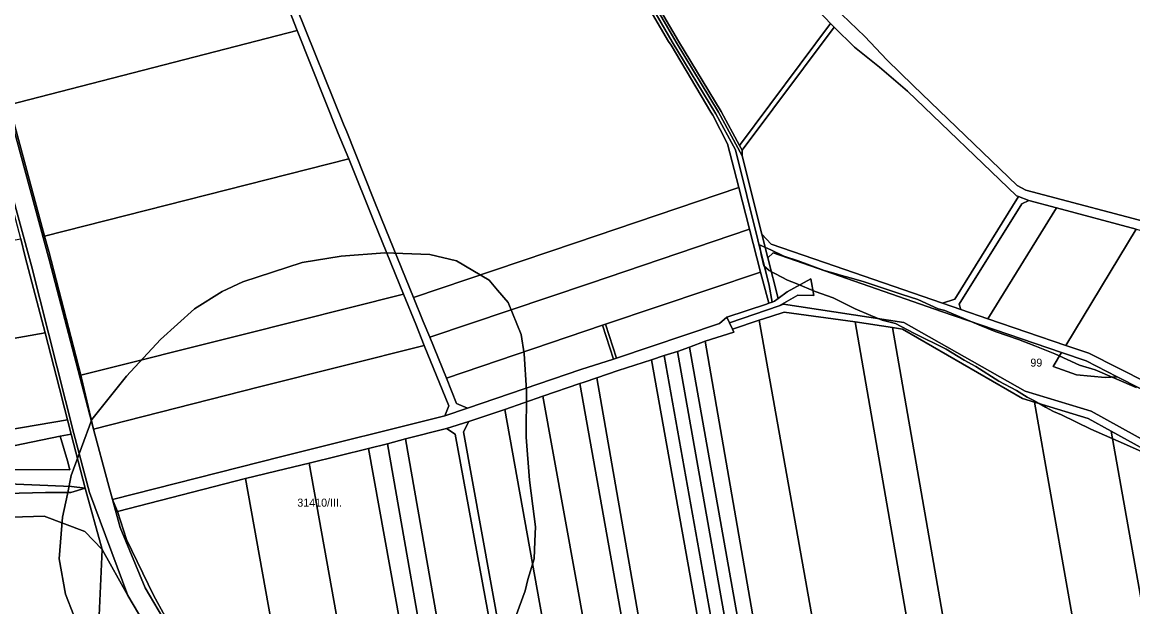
# Model space of a CAD drawing. Extents: x -541351 to -537540, y -1162694 to -1159725.
# Drawn here: x -539563 to -538870, y -1161193 to -1160828 of the extents above; entities that cross this region are included whole.
import ezdxf

# ---------------------------------------------------------------- set-up
doc = ezdxf.new("R2010")
doc.units = 0
for name, color, linetype in [('95560013', 7, 'Continuous'), ('95590013', 7, 'Continuous'), ('95600013', 7, 'Continuous'), ('95610013', 7, 'Continuous'), ('95620013', 7, 'Continuous'), ('95630013', 7, 'Continuous'), ('95640013', 7, 'Continuous'), ('95660013', 7, 'Continuous')]:
    doc.layers.add(name, color=color, linetype=linetype)

msp = doc.modelspace()

# ---------------------------------------------------------------- linework, layer by layer
at = {"layer": '95560013'}
for points in [[(-538936.41, -1160932.83), (-538941.86, -1160929.93), (-539006.76, -1160867.53), (-539023.31, -1160851.37), (-539036.93, -1160836.79), (-539051.37, -1160823.12), (-539062.82, -1160809.24), (-539062.72, -1160804.09), (-539047.66, -1160784.3), (-538944.37, -1160644.78), (-538780.28, -1160688.55), (-538705.74, -1160708.79), (-538703.32, -1160712.7), (-538773.26, -1160973.06), (-538776.17, -1160975.29), (-538851.4, -1160955.36)], [(-539571.49, -1160879.49), (-539576.96, -1160860.94), (-539589.32, -1160816.2), (-539599.23, -1160779.87), (-539429.99, -1160738.47), (-539398.34, -1160816), (-539391.52, -1160833.04)], [(-539319, -1160999.73), (-539338.81, -1160950.75), (-539344.03, -1160937.82), (-539360.64, -1160896.43), (-539362.62, -1160891.49), (-539391.92, -1160818.73), (-539393.55, -1160815.07), (-539200.33, -1160766.57), (-539198.59, -1160770.28), (-539195.58, -1160776.25), (-539186.06, -1160794.51), (-539159.57, -1160840.01), (-539158.05, -1160842.31), (-539133.25, -1160884.16), (-539132.01, -1160885.98), (-539122.7, -1160903.87), (-539115.7, -1160931.14), (-539217.82, -1160965.59)], [(-539056.08, -1160831.08), (-539113.65, -1160907.77), (-539115.26, -1160904.98), (-539058.38, -1160828.79)], [(-539549.36, -1160961.61), (-539571.49, -1160879.49), (-539391.52, -1160833.04), (-539365.89, -1160897.32), (-539359.32, -1160913.21)], [(-538940.95, -1160936.8), (-538980.86, -1161000.78), (-538988.49, -1161003.42), (-539062.15, -1160978.04), (-539095.57, -1160966.53), (-539101.33, -1160960.2), (-539113.58, -1160911.28), (-539113.65, -1160907.77), (-539056.08, -1160831.08), (-539043.56, -1160843.53), (-539027.86, -1160856), (-539010.44, -1160871.03), (-538942.34, -1160936.25)], [(-539359.32, -1160913.21), (-539343.7, -1160952.09), (-539325.13, -1160997.71), (-539426.06, -1161023.06), (-539526.79, -1161048.34), (-539546.7, -1160971.15), (-539549.36, -1160961.61)], [(-539308.65, -1161024.67), (-539312.86, -1161014.72), (-539319, -1160999.73), (-539217.82, -1160965.59), (-539115.7, -1160931.14), (-539109.11, -1160957.17), (-539208.98, -1160991.01)], [(-538977.08, -1161007.35), (-538988.49, -1161003.42), (-538980.86, -1161000.78), (-538940.95, -1160936.8), (-538934.54, -1160939.32), (-538938.99, -1160941.25), (-538978.06, -1161004.06)], [(-538960.29, -1161013.08), (-538977.08, -1161007.35), (-538978.06, -1161004.06), (-538938.99, -1160941.25), (-538934.54, -1160939.32), (-538917.2, -1160943.93)], [(-539200.9, -1161017.09), (-539298.21, -1161050.27), (-539308.65, -1161024.67), (-539208.98, -1160991.01), (-539109.11, -1160957.17), (-539102.14, -1160984.03), (-539199, -1161016.45)], [(-538693.8, -1161093.06), (-538731.97, -1161099.47), (-538764.06, -1161100.05), (-538769.83, -1161098.84), (-538897.07, -1161034.68), (-538911.55, -1161029.73), (-538867.63, -1160957.22), (-538852.58, -1160961.1), (-538705.49, -1161000.19), (-538660, -1161012.28), (-538629.09, -1161020.49), (-538626.83, -1161024.07), (-538630.91, -1161069.95), (-538631.75, -1161079.36), (-538634.66, -1161082.91)], [(-539740.05, -1161033.33), (-539738.55, -1161002.02), (-539745.1, -1160994.72), (-539564.23, -1160963.09), (-539561.45, -1160974.35), (-539548.91, -1161021.98), (-539735.79, -1161055.02)], [(-539127.84, -1161016.1), (-539192.09, -1161037.76), (-539199, -1161016.45), (-539102.14, -1160984.03), (-539097.08, -1161003.42), (-539098.52, -1161003.9), (-539123.2, -1161012.21)], [(-539526.79, -1161048.34), (-539426.06, -1161023.06), (-539325.13, -1160997.71), (-539317.56, -1161016.54), (-539312.2, -1161029.72), (-539415.08, -1161055.7), (-539518.85, -1161082.11), (-539526.32, -1161050.29)], [(-538994.31, -1161295.03), (-539045.37, -1161294.34), (-539053.1, -1161294.23), (-539103, -1161013.98), (-539095.66, -1161011.59), (-539087.45, -1161008.9), (-539043.01, -1161015.07)], [(-539292.12, -1161065.98), (-539298.21, -1161050.27), (-539200.9, -1161017.09), (-539194.02, -1161038.27), (-539214.32, -1161044.82), (-539285.11, -1161068.9)], [(-539200.9, -1161017.09), (-539199, -1161016.45), (-539192.09, -1161037.76), (-539194.02, -1161038.27)], [(-539118.78, -1161021.38), (-539119.66, -1161019.55), (-539103, -1161013.98), (-539053.1, -1161294.23), (-539084.18, -1161293.8), (-539090.47, -1161293.43), (-539136.75, -1161027.11)], [(-538972.25, -1161295.43), (-538994.31, -1161295.03), (-539043.01, -1161015.07), (-539019.68, -1161018.63), (-538971.53, -1161295.41)], [(-539648.73, -1161061.97), (-539660.98, -1161063.8), (-539674.91, -1161065.89), (-539700.61, -1161069.8), (-539704.64, -1161070.36), (-539731.15, -1161074.48), (-539735.79, -1161055.02), (-539548.91, -1161021.98), (-539539.99, -1161056.65), (-539536.99, -1161068.99), (-539534.97, -1161076.16), (-539620.86, -1161090.73), (-539621.9, -1161085.23), (-539626.91, -1161058.7)], [(-539509.83, -1161115.28), (-539518.85, -1161082.11), (-539415.08, -1161055.7), (-539312.2, -1161029.72), (-539296.85, -1161067.44), (-539299.45, -1161073.62), (-539401.26, -1161099.09), (-539506.91, -1161125.99)], [(-539154.11, -1161033.45), (-539146.43, -1161030.83), (-539099.9, -1161293.1), (-539108, -1161292.84)], [(-539090.47, -1161293.43), (-539099.9, -1161293.1), (-539146.43, -1161030.83), (-539136.75, -1161027.11)], [(-539116.49, -1161292.48), (-539124.88, -1161292.22), (-539170.2, -1161038.79), (-539162.3, -1161036.06)], [(-539108, -1161292.84), (-539116.49, -1161292.48), (-539162.3, -1161036.06), (-539154.11, -1161033.45)], [(-539146.97, -1161291.52), (-539161.16, -1161290.98), (-539162.36, -1161290.96), (-539204.4, -1161050.02), (-539191.17, -1161045.44), (-539170.2, -1161038.79), (-539124.88, -1161292.22)], [(-539212.36, -1161052.68), (-539204.4, -1161050.02), (-539162.36, -1161290.96), (-539173.01, -1161288.87), (-539215.11, -1161053.62)], [(-539238.1, -1161061.49), (-539215.11, -1161053.62), (-539173.01, -1161288.87), (-539193.16, -1161285.12), (-539197.72, -1161284.19)], [(-538844.86, -1161298.63), (-538877.93, -1161297.24), (-538890.19, -1161296.72), (-538931.09, -1161065.09), (-538897.58, -1161075.44), (-538883.22, -1161083.36)], [(-539261.83, -1161069.68), (-539224.32, -1161278.28), (-539240.79, -1161274.83), (-539253.51, -1161272.15), (-539287.68, -1161083.7), (-539284.33, -1161077.27)], [(-539586.15, -1161096.06), (-539583.98, -1161107.12), (-539583.51, -1161109.53), (-539583.24, -1161110.91), (-539582.3, -1161115.66), (-539614.61, -1161116.17), (-539620.86, -1161090.73), (-539534.97, -1161076.16), (-539532.67, -1161085.08), (-539539.6, -1161086.5)], [(-539292.9, -1161085.27), (-539298.4, -1161081.63), (-539284.33, -1161077.27), (-539287.68, -1161083.7), (-539253.51, -1161272.15), (-539258.85, -1161270.91)], [(-539298.4, -1161081.63), (-539292.9, -1161085.27), (-539258.85, -1161270.91), (-539293.08, -1161263.8), (-539323.99, -1161088.08)], [(-538805.75, -1161126.05), (-538769.12, -1161120.18), (-538766.35, -1161119.74), (-538734.05, -1161301.26), (-538762.23, -1161300.41), (-538824.88, -1161299.47), (-538844.86, -1161298.63), (-538883.22, -1161083.36)], [(-539305.49, -1161261.12), (-539308.15, -1161260.59), (-539317.28, -1161258.8), (-539346.97, -1161094.08), (-539335.13, -1161091.14)], [(-539293.08, -1161263.8), (-539305.49, -1161261.12), (-539335.13, -1161091.14), (-539323.99, -1161088.08)], [(-539384.02, -1161103.38), (-539346.97, -1161094.08), (-539317.28, -1161258.8), (-539357.66, -1161250.4)], [(-539398.81, -1161106.88), (-539384.02, -1161103.38), (-539357.66, -1161250.4), (-539360.48, -1161249.96), (-539400.77, -1161241.37), (-539423.77, -1161112.8)], [(-539414.3, -1161238.64), (-539438.49, -1161233.39), (-539443.01, -1161208.8), (-539466.8, -1161212.37), (-539481.41, -1161185.77), (-539498.11, -1161150.86), (-539503.79, -1161133.46), (-539423.77, -1161112.8), (-539400.77, -1161241.37)], [(-539516.59, -1161225.93), (-539513.32, -1161157.12), (-539497.36, -1161186), (-539472.01, -1161228.75)]]:
    msp.add_lwpolyline(points, close=True, dxfattribs=at)
msp.add_lwpolyline([(-539391.92, -1160818.73), (-539362.62, -1160891.49), (-539360.64, -1160896.43), (-539344.03, -1160937.82), (-539338.81, -1160950.75), (-539319, -1160999.73), (-539312.86, -1161014.72), (-539308.65, -1161024.67), (-539298.21, -1161050.27), (-539292.12, -1161065.98), (-539285.11, -1161068.9), (-539299.45, -1161073.62), (-539296.85, -1161067.44), (-539312.2, -1161029.72), (-539317.56, -1161016.54), (-539325.13, -1160997.71), (-539343.7, -1160952.09), (-539359.32, -1160913.21), (-539365.89, -1160897.32), (-539391.52, -1160833.04), (-539398.34, -1160816)], dxfattribs=at)
at = {"layer": '95590013'}
msp.add_lwpolyline([(-539513.32, -1161157.12), (-539516.59, -1161225.93), (-539557.69, -1161223.11), (-539601.36, -1161219.9), (-539597.06, -1161137.85), (-539549.61, -1161136.48), (-539524.21, -1161145.9)], close=True, dxfattribs=at)
at = {"layer": '95600013'}
msp.add_lwpolyline([(-538917.2, -1160943.93), (-538867.63, -1160957.22), (-538911.55, -1161029.73), (-538960.29, -1161013.08)], close=True, dxfattribs=at)
at = {"layer": '95610013'}
for points in [[(-539083, -1160802.43), (-539058.38, -1160828.79), (-539115.26, -1160904.98), (-539126.83, -1160883.61), (-539153.38, -1160839.71), (-539168.09, -1160814.49), (-539123.11, -1160753.62), (-539110.17, -1160768.73), (-539097.29, -1160783.9)], [(-538933.47, -1161294.66), (-538968.85, -1161295.34), (-538971.53, -1161295.41), (-539019.68, -1161018.63), (-539013.52, -1161019.58), (-538938.47, -1161062.83), (-538931.09, -1161065.09), (-538890.19, -1161296.72)], [(-539261.83, -1161069.68), (-539238.1, -1161061.49), (-539197.72, -1161284.19), (-539224.32, -1161278.28)]]:
    msp.add_lwpolyline(points, close=True, dxfattribs=at)
at = {"layer": '95620013'}
msp.add_lwpolyline([(-538809.39, -1161118.52), (-538895.58, -1161070.78), (-538936.84, -1161058.37), (-539012.62, -1161015.43), (-539087.9, -1161004.04), (-539090.53, -1161004.95), (-539078.96, -1160998.33), (-539068.78, -1160998.52), (-539070.83, -1160988.11), (-539085.49, -1160996.3), (-539091.23, -1161000.54), (-539097.61, -1160975.07), (-539094.17, -1160972.03), (-539061.97, -1160983.19), (-539016.01, -1160999.12), (-538989.05, -1161008.47), (-538914.19, -1161034.17), (-538919.34, -1161042.88), (-538904.81, -1161048.05), (-538886.83, -1161049.88), (-538879.44, -1161049.27), (-538835.45, -1161071.57)], dxfattribs=at)
msp.add_lwpolyline([(-538898.78, -1161039.46), (-538879.44, -1161049.27), (-538886.83, -1161049.88), (-538904.81, -1161048.05), (-538919.34, -1161042.88), (-538914.19, -1161034.17)], close=True, dxfattribs=at)
at = {"layer": '95630013'}
msp.add_lwpolyline([(-539113.65, -1160907.77), (-539113.58, -1160911.28), (-539128.35, -1160884.12), (-539154.76, -1160840.33), (-539182.33, -1160792.82), (-539190.9, -1160773.73), (-539198.32, -1160759.07), (-539205.22, -1160742.97), (-539196.85, -1160758.33), (-539196.09, -1160759.86), (-539189.5, -1160773.11), (-539180.96, -1160792.07), (-539168.09, -1160814.49), (-539153.38, -1160839.71), (-539126.83, -1160883.61), (-539115.26, -1160904.98)], close=True, dxfattribs=at)
at = {"layer": '95640013'}
for points in [[(-539623.5, -1160743.95), (-539590.55, -1160859.01), (-539557.57, -1160980.12), (-539531.01, -1161084.78), (-539521.39, -1161121.63), (-539497.36, -1161186), (-539513.32, -1161157.12), (-539523.97, -1161118.87), (-539532.67, -1161085.08), (-539534.97, -1161076.16), (-539536.99, -1161068.99), (-539539.99, -1161056.65), (-539548.91, -1161021.98), (-539561.45, -1160974.35), (-539564.23, -1160963.09), (-539571.68, -1160934.67), (-539574.11, -1160925.41), (-539578.21, -1160910), (-539583.93, -1160888.29), (-539585.53, -1160883.06), (-539590.37, -1160867.23), (-539602.29, -1160823.36)], [(-539589.32, -1160816.2), (-539576.96, -1160860.94), (-539571.49, -1160879.49), (-539549.36, -1160961.61), (-539546.7, -1160971.15), (-539526.79, -1161048.34), (-539526.32, -1161050.29), (-539518.85, -1161082.11), (-539546.37, -1160976.85), (-539579.46, -1160855.53), (-539611.99, -1160740.35)], [(-539184.32, -1160793.64), (-539157.26, -1160840.13), (-539130.18, -1160885.05), (-539117.85, -1160907.69), (-539096.68, -1160992.38), (-539094.8, -1161002.65), (-539097.08, -1161003.42), (-539102.14, -1160984.03), (-539109.11, -1160957.17), (-539115.7, -1160931.14), (-539122.7, -1160903.87), (-539132.01, -1160885.98), (-539133.25, -1160884.16), (-539158.05, -1160842.31), (-539159.57, -1160840.01), (-539186.06, -1160794.51)], [(-539182.33, -1160792.82), (-539154.76, -1160840.33), (-539128.35, -1160884.12), (-539113.58, -1160911.28), (-539101.33, -1160960.2), (-539097.61, -1160975.07), (-539091.23, -1161000.54), (-539093.5, -1161002.21), (-539094.8, -1161002.65), (-539096.68, -1160992.38), (-539117.85, -1160907.69), (-539130.18, -1160885.05), (-539157.26, -1160840.13), (-539184.32, -1160793.64)], [(-538867.63, -1160957.22), (-538917.2, -1160943.93), (-538934.54, -1160939.32), (-538940.95, -1160936.8), (-538942.34, -1160936.25), (-539010.44, -1160871.03), (-539027.86, -1160856), (-539043.56, -1160843.53), (-539056.08, -1160831.08), (-539058.38, -1160828.79), (-539083, -1160802.43)], [(-539051.37, -1160823.12), (-539036.93, -1160836.79), (-539023.31, -1160851.37), (-539006.76, -1160867.53), (-538941.86, -1160929.93), (-538936.41, -1160932.83), (-538851.4, -1160955.36)], [(-539579.46, -1160855.53), (-539546.37, -1160976.85), (-539518.85, -1161082.11), (-539509.83, -1161115.28), (-539506.91, -1161125.99), (-539502.19, -1161143.36), (-539486.6, -1161181.18), (-539456.83, -1161231.51), (-539439.15, -1161260.76), (-539423.55, -1161284.51), (-539371.3, -1161375.32), (-539361.37, -1161392.57), (-539352.75, -1161410.03), (-539343.67, -1161428.41), (-539341.16, -1161434.73), (-539313.61, -1161504.16), (-539309.76, -1161510.68), (-539308.92, -1161512.11), (-539308.09, -1161513.51), (-539309.47, -1161514.21), (-539307.78, -1161514.67), (-539303.69, -1161529.93)], [(-539297.21, -1161624.42), (-539322.59, -1161523.59), (-539356.24, -1161433.35), (-539372.91, -1161399.14), (-539392.4, -1161365.24), (-539405.14, -1161343.09), (-539434.98, -1161291.19), (-539447.73, -1161269.69), (-539468.39, -1161234.85), (-539472.01, -1161228.75), (-539497.36, -1161186), (-539521.39, -1161121.63), (-539531.01, -1161084.78), (-539557.57, -1160980.12), (-539590.55, -1160859.01)], [(-538835.45, -1161071.57), (-538879.44, -1161049.27), (-538898.78, -1161039.46), (-538914.19, -1161034.17), (-538989.05, -1161008.47), (-539016.01, -1160999.12), (-539061.97, -1160983.19), (-539094.17, -1160972.03), (-539097.61, -1160975.07), (-539101.33, -1160960.2), (-539095.57, -1160966.53), (-539062.15, -1160978.04), (-538988.49, -1161003.42), (-538977.08, -1161007.35), (-538960.29, -1161013.08), (-538911.55, -1161029.73), (-538897.07, -1161034.68), (-538769.83, -1161098.84)], [(-538805.75, -1161126.05), (-538883.22, -1161083.36), (-538897.58, -1161075.44), (-538931.09, -1161065.09), (-538938.47, -1161062.83), (-539013.52, -1161019.58), (-539019.68, -1161018.63), (-539043.01, -1161015.07), (-539087.45, -1161008.9), (-539095.66, -1161011.59), (-539103, -1161013.98), (-539119.66, -1161019.55), (-539121.56, -1161015.62), (-539090.53, -1161004.95), (-539087.9, -1161004.04), (-539012.62, -1161015.43), (-538936.84, -1161058.37), (-538895.58, -1161070.78), (-538809.39, -1161118.52)]]:
    msp.add_lwpolyline(points, dxfattribs=at)
for points in [[(-539070.83, -1160988.11), (-539068.78, -1160998.52), (-539078.96, -1160998.33), (-539090.53, -1161004.95), (-539121.56, -1161015.62), (-539123.2, -1161012.21), (-539098.52, -1161003.9), (-539097.08, -1161003.42), (-539094.8, -1161002.65), (-539093.5, -1161002.21), (-539091.23, -1161000.54), (-539085.49, -1160996.3)], [(-539384.02, -1161103.38), (-539398.81, -1161106.88), (-539423.77, -1161112.8), (-539503.79, -1161133.46), (-539506.91, -1161125.99), (-539401.26, -1161099.09), (-539299.45, -1161073.62), (-539285.11, -1161068.9), (-539214.32, -1161044.82), (-539194.02, -1161038.27), (-539192.09, -1161037.76), (-539127.84, -1161016.1), (-539123.2, -1161012.21), (-539121.56, -1161015.62), (-539119.66, -1161019.55), (-539118.78, -1161021.38), (-539136.75, -1161027.11), (-539146.43, -1161030.83), (-539154.11, -1161033.45), (-539162.3, -1161036.06), (-539170.2, -1161038.79), (-539191.17, -1161045.44), (-539204.4, -1161050.02), (-539212.36, -1161052.68), (-539215.11, -1161053.62), (-539238.1, -1161061.49), (-539261.83, -1161069.68), (-539284.33, -1161077.27), (-539298.4, -1161081.63), (-539323.99, -1161088.08), (-539335.13, -1161091.14), (-539346.97, -1161094.08)], [(-539568.93, -1161107.22), (-539583.98, -1161107.12), (-539586.15, -1161096.06), (-539539.6, -1161086.5), (-539535.14, -1161101.86), (-539533.52, -1161107.45)], [(-539578.89, -1161113.3), (-539578.03, -1161113.12), (-539578.7, -1161110.03), (-539583.24, -1161110.91), (-539583.51, -1161109.53), (-539583.98, -1161107.12), (-539568.93, -1161107.22), (-539533.52, -1161107.45), (-539535.14, -1161101.86), (-539539.6, -1161086.5), (-539532.67, -1161085.08), (-539523.97, -1161118.87), (-539532.52, -1161117.9), (-539577.02, -1161115.9), (-539577.21, -1161114.26), (-539578.74, -1161114.48)], [(-539604.51, -1161138.05), (-539665.41, -1161141.98), (-539671.19, -1161142.35), (-539672.02, -1161138.53), (-539696.7, -1161140.71), (-539704.68, -1161133.8), (-539704.71, -1161133.18), (-539691.46, -1161131.59), (-539682.76, -1161130.41), (-539661.1, -1161127.89), (-539647.02, -1161126.43), (-539613.08, -1161122.91), (-539606.5, -1161123.02), (-539548.77, -1161121.52), (-539533.04, -1161121.61), (-539523.97, -1161118.87), (-539513.32, -1161157.12), (-539524.21, -1161145.9), (-539549.61, -1161136.48), (-539597.06, -1161137.85)], [(-539606.5, -1161123.02), (-539613.08, -1161122.91), (-539614.61, -1161116.17), (-539582.3, -1161115.66), (-539577.02, -1161115.9), (-539532.52, -1161117.9), (-539523.97, -1161118.87), (-539533.04, -1161121.61), (-539548.77, -1161121.52)], [(-539439.15, -1161260.76), (-539456.83, -1161231.51), (-539486.6, -1161181.18), (-539502.19, -1161143.36), (-539506.91, -1161125.99), (-539503.79, -1161133.46), (-539498.11, -1161150.86), (-539481.41, -1161185.77), (-539466.8, -1161212.37), (-539464.98, -1161215.56), (-539461.28, -1161222.06), (-539455.45, -1161227.46), (-539434.61, -1161261.23), (-539392.78, -1161333.67), (-539371.3, -1161375.32), (-539423.55, -1161284.51)]]:
    msp.add_lwpolyline(points, close=True, dxfattribs=at)
at = {"layer": '95660013'}
for points in [[(-538867.62, -1161056), (-538893.12, -1161045), (-538902.87, -1161042), (-538918.31, -1161035), (-538930.87, -1161030), (-538941.12, -1161026), (-538955.62, -1161021), (-538965.81, -1161017), (-538987.12, -1161008), (-538991.31, -1161007), (-539003.81, -1161001), (-539013.62, -1160998), (-539037.37, -1160990), (-539045.33, -1160987.78), (-539051.69, -1160986), (-539056.44, -1160984.67), (-539062.37, -1160983), (-539078.62, -1160977), (-539087.62, -1160974), (-539095.81, -1160970), (-539102.81, -1160967), (-539101.62, -1160974), (-539100.83, -1160977.33), (-539100.19, -1160980), (-539096.81, -1160983), (-539085.37, -1160989), (-539079.87, -1160991), (-539068, -1160996), (-539056.81, -1161000), (-539043.12, -1161007), (-539033.31, -1161011), (-539026.12, -1161014), (-539017.81, -1161016), (-539006.31, -1161022), (-538986.12, -1161032), (-538975, -1161039), (-538967.62, -1161043), (-538953.31, -1161052), (-538942.37, -1161058), (-538935.62, -1161062), (-538931.49, -1161064.22), (-538928.19, -1161066), (-538924.16, -1161068.22), (-538919.12, -1161071), (-538914.12, -1161073), (-538895.81, -1161082), (-538875.37, -1161091), (-538862, -1161097)], [(-538862, -1161097), (-538875.37, -1161091), (-538895.81, -1161082), (-538914.12, -1161073), (-538919.12, -1161071), (-538924.16, -1161068.22), (-538928.19, -1161066), (-538931.49, -1161064.22), (-538935.62, -1161062), (-538942.37, -1161058), (-538953.31, -1161052), (-538967.62, -1161043), (-538975, -1161039), (-538986.12, -1161032), (-539006.31, -1161022), (-539017.81, -1161016), (-539026.12, -1161014), (-539033.31, -1161011), (-539043.12, -1161007), (-539056.81, -1161000), (-539068, -1160996), (-539079.87, -1160991), (-539085.37, -1160989), (-539096.81, -1160983), (-539100.19, -1160980), (-539100.83, -1160977.33), (-539101.62, -1160974), (-539102.81, -1160967), (-539095.81, -1160970), (-539087.62, -1160974), (-539078.62, -1160977), (-539062.37, -1160983), (-539056.44, -1160984.67), (-539051.69, -1160986), (-539045.33, -1160987.78), (-539037.37, -1160990), (-539013.62, -1160998), (-539003.81, -1161001), (-538991.31, -1161007), (-538987.12, -1161008), (-538965.81, -1161017), (-538955.62, -1161021), (-538941.12, -1161026), (-538930.87, -1161030), (-538918.31, -1161035), (-538902.87, -1161042), (-538893.12, -1161045), (-538867.62, -1161056)], [(-539259.87, -1161212), (-539249.12, -1161183), (-539247.5, -1161176), (-539243.62, -1161163), (-539243.1, -1161151.89), (-539242.69, -1161143), (-539244.33, -1161130.11), (-539246.37, -1161114), (-539248.5, -1161087), (-539248.31, -1161058), (-539249.87, -1161035), (-539251.62, -1161023), (-539259.87, -1161003), (-539266.44, -1160995.22), (-539271.69, -1160989), (-539292, -1160977), (-539308.62, -1160973), (-539336.81, -1160972), (-539364.12, -1160974), (-539388.5, -1160978), (-539425.62, -1160990), (-539438.37, -1160996), (-539455.81, -1161007), (-539476.87, -1161026), (-539498.12, -1161049), (-539519.81, -1161076), (-539532.69, -1161111), (-539535.1, -1161122.56), (-539538.12, -1161137), (-539540.31, -1161163), (-539536.19, -1161185), (-539531.05, -1161198.33)], [(-539531.05, -1161198.33), (-539536.19, -1161185), (-539540.31, -1161163), (-539538.12, -1161137), (-539535.1, -1161122.56), (-539532.69, -1161111), (-539519.81, -1161076), (-539498.12, -1161049), (-539476.87, -1161026), (-539455.81, -1161007), (-539438.37, -1160996), (-539425.62, -1160990), (-539388.5, -1160978), (-539364.12, -1160974), (-539336.81, -1160972), (-539308.62, -1160973), (-539292, -1160977), (-539271.69, -1160989), (-539266.44, -1160995.22), (-539259.87, -1161003), (-539251.62, -1161023), (-539249.87, -1161035), (-539248.31, -1161058), (-539248.5, -1161087), (-539246.37, -1161114), (-539244.33, -1161130.11), (-539242.69, -1161143), (-539243.1, -1161151.89), (-539243.62, -1161163), (-539247.5, -1161176), (-539249.12, -1161183), (-539259.87, -1161212)]]:
    msp.add_lwpolyline(points, dxfattribs=at)

# ---------------------------------------------------------------- texts
for s, p in [('99', (-538933.62, -1161043)), ('31410/III.', (-539391.5, -1161130.44))]:
    msp.add_text(s, height=5, rotation=0, dxfattribs=at).set_placement(p)

doc.saveas('drawing.dxf')
